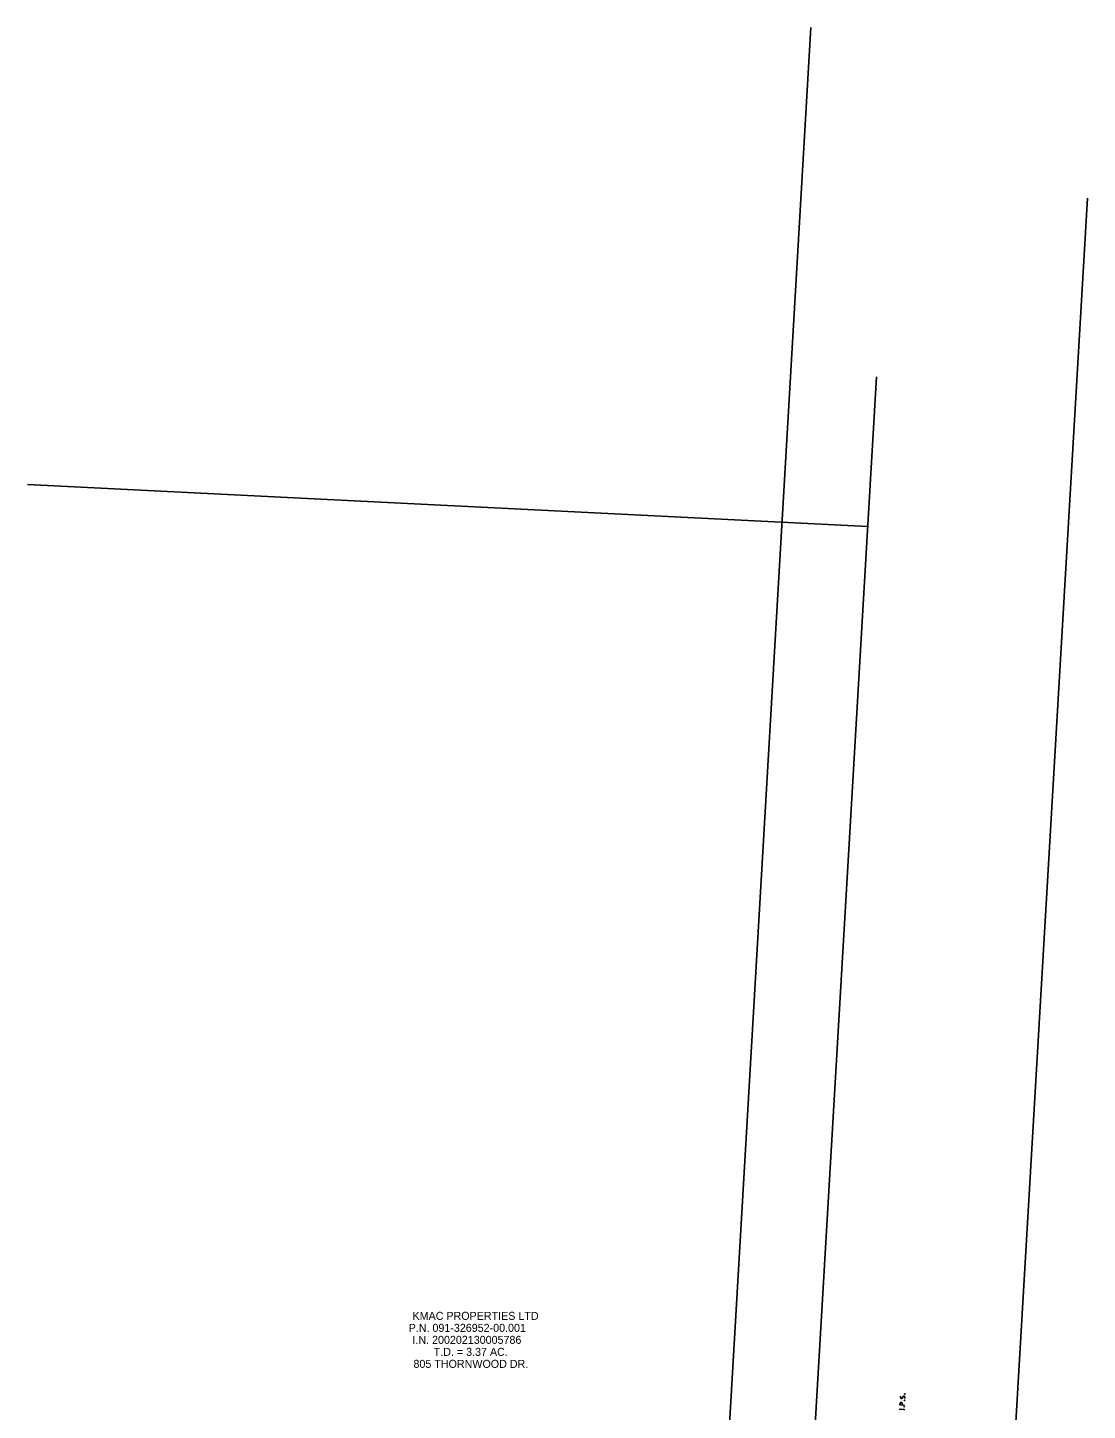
# Model space of a CAD drawing. Extents: x 1972534 to 2012581, y 730948 to 738786.
# Drawn here: x 1973796 to 1974166.8, y 738301.6 to 738785.5 of the extents above; entities that cross this region are included whole.
import ezdxf

# ---------------------------------------------------------------- set-up
doc = ezdxf.new("R2010")
doc.units = 0
for name, color, linetype in [('_CIVIL_CONSTRUCTION', 7, 'Continuous'), ('DR_P_GenericNode', 7, 'Continuous'), ('GE_X_Alignment_1000_Cardinal_Points', 7, 'Continuous'), ('PF_X_Ground_Line', 7, 'Continuous'), ('UT_P_Water', 7, 'Continuous'), ('UT_P_Water_Cells', 7, 'Continuous')]:
    doc.layers.add(name, color=color, linetype=linetype)

msp = doc.modelspace()

# ---------------------------------------------------------------- linework, layer by layer
at = {"layer": 'DR_P_GenericNode'}
for points in [[(1974101.5, 738306.55), (1974101.47, 738306.53), (1974101.45, 738306.5), (1974101.4, 738306.4), (1974101.37, 738306.28), (1974101.37, 738306.2), (1974101.36, 738306.16), (1974101.39, 738306.02), (1974101.46, 738305.89), (1974101.56, 738305.81), (1974101.66, 738305.78), (1974101.73, 738305.78), (1974101.84, 738305.79), (1974101.93, 738305.88), (1974102.34, 738306.46), (1974102.39, 738306.51), (1974102.44, 738306.53), (1974102.52, 738306.55), (1974102.6, 738306.55), (1974102.67, 738306.53), (1974102.72, 738306.52), (1974102.78, 738306.49), (1974102.83, 738306.47), (1974102.87, 738306.44), (1974102.9, 738306.41), (1974102.93, 738306.37), (1974102.95, 738306.33), (1974102.96, 738306.29), (1974102.97, 738306.19), (1974102.96, 738306.04), (1974102.93, 738305.94), (1974102.83, 738305.8), (1974102.75, 738305.72)], [(1974102.82, 738307.3), (1974102.82, 738307.35), (1974102.85, 738307.38), (1974102.9, 738307.41), (1974102.96, 738307.41), (1974103.01, 738307.37), (1974103.03, 738307.34), (1974103.03, 738307.28), (1974103, 738307.25), (1974102.95, 738307.22), (1974102.89, 738307.23), (1974102.84, 738307.26), (1974102.82, 738307.3)], [(1974101.12, 738301.82), (1974101.14, 738302.17)], [(1974102.73, 738301.9), (1974101.13, 738301.99)], [(1974102.82, 738303.46), (1974101.22, 738303.55), (1974101.25, 738304.08), (1974101.26, 738304.14), (1974101.29, 738304.21), (1974101.32, 738304.24), (1974101.35, 738304.28), (1974101.41, 738304.32), (1974101.48, 738304.35), (1974101.58, 738304.36), (1974101.73, 738304.35), (1974101.78, 738304.34), (1974101.85, 738304.31), (1974101.94, 738304.26), (1974101.97, 738304.22), (1974102, 738304.18), (1974102.02, 738304.13), (1974102.03, 738304.04), (1974102, 738303.51)], [(1974102.57, 738302.87), (1974102.57, 738302.93), (1974102.6, 738302.96), (1974102.65, 738302.99), (1974102.71, 738302.98), (1974102.76, 738302.95), (1974102.78, 738302.91), (1974102.78, 738302.86), (1974102.75, 738302.83), (1974102.7, 738302.8), (1974102.64, 738302.8), (1974102.59, 738302.84), (1974102.57, 738302.87)], [(1974102.69, 738305.12), (1974102.7, 738305.17), (1974102.72, 738305.2), (1974102.78, 738305.23), (1974102.84, 738305.23), (1974102.89, 738305.19), (1974102.91, 738305.16), (1974102.91, 738305.1), (1974102.88, 738305.07), (1974102.83, 738305.04), (1974102.77, 738305.05), (1974102.72, 738305.08), (1974102.69, 738305.12)], [(1974102.72, 738301.73), (1974102.74, 738302.08)]]:
    msp.add_lwpolyline(points, dxfattribs=at)
at = {"layer": 'GE_X_Alignment_1000_Cardinal_Points'}
msp.add_line((1974031.44, 738123.95), (1974070.08, 738785.54), dxfattribs=at)
at = {"layer": 'PF_X_Ground_Line'}
msp.add_line((1974061.39, 738122.22), (1974092.99, 738663.34), dxfattribs=at)
at = {"layer": 'UT_P_Water'}
msp.add_line((1974089.93, 738610.92), (1973796.04, 738625.63), dxfattribs=at)
at = {"layer": 'UT_P_Water_Cells'}
msp.add_line((1974141.74, 738297.49), (1974166.77, 738725.89), dxfattribs=at)

# ---------------------------------------------------------------- texts
at = {"layer": '_CIVIL_CONSTRUCTION'}
for s, p in [('KMAC PROPERTIES LTD', (1973930.68, 738333.29)), ('P.N. 091-326952-00.001', (1973929.34, 738329.09)), ('I.N. 200202130005786', (1973930.66, 738324.89)), ('T.D. = 3.37 AC.', (1973938.1, 738320.69)), ('805 THORNWOOD DR.', (1973931.02, 738316.49))]:
    msp.add_text(s, height=2.8, dxfattribs=at).set_placement(p)

doc.saveas('drawing.dxf')
